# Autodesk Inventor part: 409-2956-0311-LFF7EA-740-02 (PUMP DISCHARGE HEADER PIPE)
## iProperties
Created: 2010-06
Part Number: 409-2956-0311-LFF7EA-740-02 (PUMP DISCHARGE HEADER PIPE)
Material: Sch40 CS PIPE SEAMLESS
Description: PIPE
Document SubType Name: Modeling
Designer: S. Boerckel
Engineer: Steve Boerckel
Mass: 6532.87 g
Surface Area: 2805.88 cm^2
Volume: 832.213 cm^3
Density: 7.85 g/cm^3
Cost Center: 4"
SMR: =<COST CENTER> - <Material>
Length: 16.000 in
Title: 4"
Author: S. Boerckel
Revision Number: B
Subject: DEMIN WATER FORWARDING PUMP SKID-7EA
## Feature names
1. Extrusion1
